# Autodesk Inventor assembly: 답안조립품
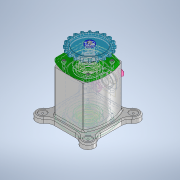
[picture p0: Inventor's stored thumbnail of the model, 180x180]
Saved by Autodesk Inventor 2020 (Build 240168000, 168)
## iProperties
Created: 2022-01
Part Number: 답안조립품
Document SubType Name: Assembly
Designer: USER
Author: USER
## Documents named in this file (13)
- C:\Users\USER\Desktop\720106V1028\OldVersions\답안조립품.iam
- C:\Users\USER\Desktop\720106V1028\본체.ipt
- C:\Users\USER\Desktop\720106V1028\베어링 6203.ipt
- C:\Users\USER\Desktop\720106V1028\볼트 M4 x 12.ipt
- C:\Users\USER\Desktop\720106V1028\부시.ipt
- C:\Users\USER\Desktop\720106V1028\스프로킷.ipt
- C:\Users\USER\Desktop\720106V1028\슬라이더.ipt
- C:\Users\USER\Desktop\720106V1028\오일 실 17 x 30 x 8.ipt
- C:\Users\USER\Desktop\720106V1028\와셔 4 x 20.ipt
- C:\Users\USER\Desktop\720106V1028\육각머리볼트 M4.ipt
- C:\Users\USER\Desktop\720106V1028\커버.ipt
- C:\Users\USER\Desktop\720106V1028\키 5 x 5.ipt
- C:\Users\USER\Desktop\720106V1028\편심축.ipt
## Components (8 placed, 1 different names)
1. M4x0.7x12:1
2. M4x0.7x12:2
3. M4x0.7x12:3
4. M4x0.7x12:4
5. M4x0.7x12:5
6. M4x0.7x12:7
7. M4x0.7x12:8
8. M4x0.7x12:9
